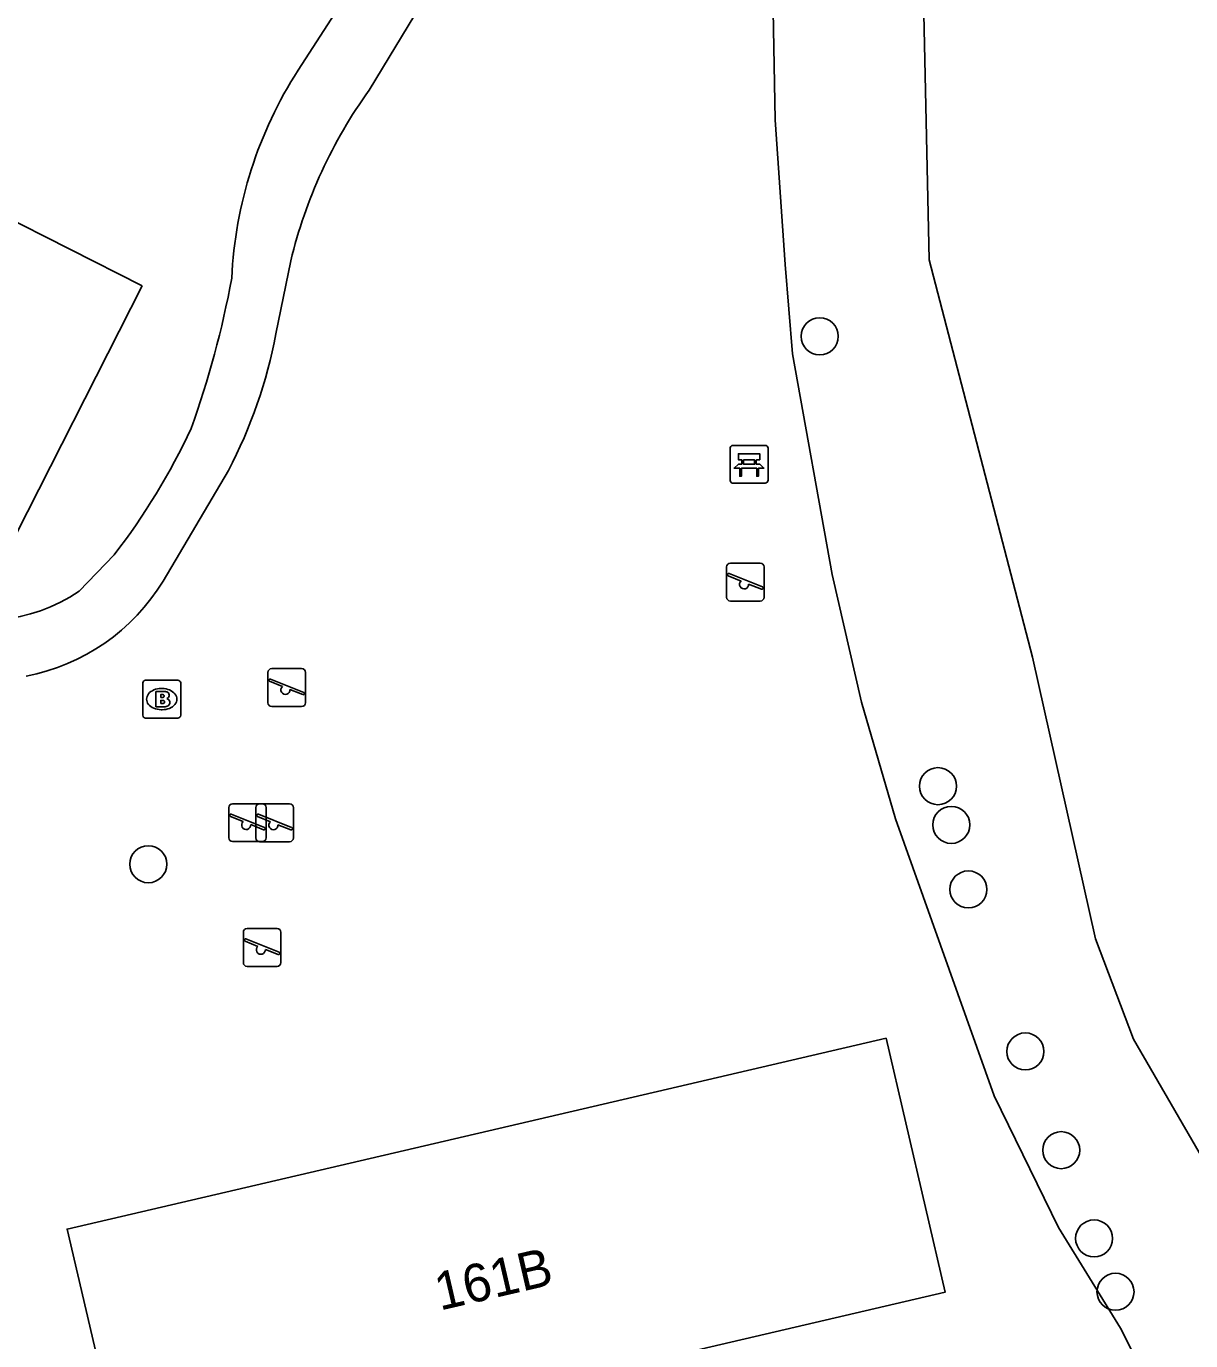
# Model space of a CAD drawing. Extents: x 160203 to 161526, y 379529 to 381797.
# Drawn here: x 161221.44 to 161252.18, y 381451.92 to 381486.62 of the extents above; entities that cross this region are included whole.
import ezdxf

# ---------------------------------------------------------------- set-up
doc = ezdxf.new("R2010")
doc.units = 0
for name, color, linetype in [('IMGEO_Bank', 7, 'Continuous'), ('IMGEO_Boom', 7, 'Continuous'), ('IMGEO_Brandkraan', 7, 'Continuous'), ('IMGEO_Groenvoorziening', 7, 'Continuous'), ('IMGEO_Pand', 7, 'Continuous'), ('IMGEO_Pand_nummerreeks', 7, 'Continuous'), ('IMGEO_Speelvoorziening', 7, 'Continuous'), ('IMGEO_Voetpad_halfverhard', 7, 'Continuous'), ('IMGEO_Waterloop', 7, 'Continuous')]:
    doc.layers.add(name, color=color, linetype=linetype)

msp = doc.modelspace()

# ---------------------------------------------------------------- linework, layer by layer
at = {"layer": 'IMGEO_Bank'}
for p, q in [((161240.024, 381474.633), (161240.024, 381475.474)), ((161240.024, 381475.474), (161240.024, 381474.633)), ((161240.099, 381475.558), (161240.94, 381475.558)), ((161240.94, 381475.558), (161240.099, 381475.558)), ((161241.024, 381475.483), (161241.024, 381474.642)), ((161241.024, 381474.642), (161241.024, 381475.483)), ((161240.333, 381475.064), (161240.333, 381475.17)), ((161240.377, 381475.17), (161240.377, 381475.064)), ((161240.665, 381475.176), (161240.383, 381475.176)), ((161240.671, 381475.064), (161240.671, 381475.17)), ((161240.715, 381475.17), (161240.715, 381475.064)), ((161240.721, 381474.956), (161240.328, 381474.956)), ((161240.383, 381475.058), (161240.665, 381475.058)), ((161240.949, 381474.558), (161240.108, 381474.558)), ((161240.108, 381474.558), (161240.949, 381474.558))]:
    msp.add_line(p, q, dxfattribs=at)
for points in [[(161240.327, 381475.176), (161240.241, 381475.176), (161240.241, 381475.337), (161240.804, 381475.337), (161240.804, 381475.176), (161240.721, 381475.176)], [(161240.271, 381474.956), (161240.129, 381474.956), (161240.241, 381475.058), (161240.327, 381475.058)], [(161240.321, 381474.949), (161240.321, 381474.742), (161240.278, 381474.742), (161240.278, 381474.949)], [(161240.721, 381475.058), (161240.804, 381475.058), (161240.916, 381474.956), (161240.777, 381474.956)], [(161240.771, 381474.949), (161240.771, 381474.742), (161240.727, 381474.742), (161240.727, 381474.949)]]:
    msp.add_lwpolyline(points, dxfattribs=at)
for centre, radius, start, end in [((161240.102, 381475.48), 0.0779, 92.4484, 184.2845), ((161240.102, 381475.48), 0.0779, 92.4484, 184.2845), ((161240.946, 381475.48), 0.0779, 2.4484, 94.2845), ((161240.946, 381475.48), 0.0779, 2.4484, 94.2845), ((161240.326, 381475.169), 0.00671, 2.8957, 87.1043), ((161240.383, 381475.169), 0.00671, 92.8957, 177.1043), ((161240.665, 381475.169), 0.00671, 2.8957, 87.1043), ((161240.722, 381475.169), 0.00671, 92.8957, 177.1043), ((161240.271, 381474.949), 0.00671, 2.8957, 87.1043), ((161240.328, 381474.949), 0.00671, 92.8957, 177.1043), ((161240.326, 381475.065), 0.00671, 272.8957, 357.1043), ((161240.383, 381475.065), 0.00671, 182.8957, 267.1043), ((161240.665, 381475.065), 0.00671, 272.8957, 357.1043), ((161240.722, 381475.065), 0.00671, 182.8957, 267.1043), ((161240.72, 381474.949), 0.00671, 2.8957, 87.1043), ((161240.777, 381474.949), 0.00671, 92.8957, 177.1043), ((161240.102, 381474.636), 0.0779, 182.4484, 274.2845), ((161240.102, 381474.636), 0.0779, 182.4484, 274.2845), ((161240.946, 381474.636), 0.0779, 272.4484, 4.2845), ((161240.946, 381474.636), 0.0779, 272.4484, 4.2845)]:
    msp.add_arc(centre, radius, start, end, dxfattribs=at)
at = {"layer": 'IMGEO_Boom'}
for centre in [(161242.389, 381478.437), (161245.511, 381466.559), (161245.862, 381465.537), (161224.663, 381464.498), (161246.314, 381463.832), (161247.818, 381459.553), (161248.765, 381456.947), (161249.632, 381454.617), (161250.198, 381453.207)]:
    msp.add_circle(centre, 0.489, dxfattribs=at)
at = {"layer": 'IMGEO_Brandkraan'}
for p, q in [((161224.517, 381468.431), (161224.517, 381469.283)), ((161224.592, 381469.357), (161225.444, 381469.357)), ((161225.518, 381469.283), (161225.518, 381468.431)), ((161225.005, 381469.137), (161225.03, 381469.137)), ((161225.028, 381468.577), (161225.003, 381468.577)), ((161225.444, 381468.357), (161224.592, 381468.357))]:
    msp.add_line(p, q, dxfattribs=at)
for points in [[(161224.517, 381468.431), (161224.517, 381469.283)], [(161224.592, 381469.357), (161225.444, 381469.357)], [(161225.518, 381469.283), (161225.518, 381468.431)], [(161224.865, 381469.057), (161224.865, 381468.657), (161225.078, 381468.657)], [(161225.096, 381469.057), (161224.865, 381469.057)], [(161225.044, 381468.976), (161224.99, 381468.976), (161224.99, 381468.9)], [(161224.99, 381468.9), (161225.043, 381468.9)], [(161225.052, 381468.824), (161224.99, 381468.824), (161224.99, 381468.743)], [(161224.99, 381468.743), (161225.052, 381468.743)], [(161225.444, 381468.357), (161224.592, 381468.357)]]:
    msp.add_lwpolyline(points, dxfattribs=at)
for centre, radius, start, end in [((161224.594, 381469.281), 0.0765, 91.552, 178.448), ((161224.594, 381469.281), 0.0765, 91.552, 178.448), ((161225.442, 381469.281), 0.0765, 1.552, 88.448), ((161225.442, 381469.281), 0.0765, 1.552, 88.448), ((161225.045, 381468.938), 0.0379, 267.8285, 90.9355), ((161225.1, 381468.912), 0.145, 59.4692, 91.5367), ((161225.125, 381468.959), 0.0922, 285.5137, 58.1501), ((161225.13, 381468.767), 0.105, 301.3115, 78.989), ((161225.053, 381468.783), 0.0404, 269.8759, 90.5077), ((161225.084, 381468.908), 0.251, 268.6676, 293.5347), ((161224.594, 381468.433), 0.0765, 181.552, 268.448), ((161224.594, 381468.433), 0.0765, 181.552, 268.448), ((161225.442, 381468.433), 0.0765, 271.552, 358.448), ((161225.442, 381468.433), 0.0765, 271.552, 358.448)]:
    msp.add_arc(centre, radius, start, end, dxfattribs=at)
for centre, major_axis, ratio, start_param, end_param in [((161225.004, 381468.857), (-0.387, 0.002), 0.722429, 4.712389, 7.853982), ((161225.029, 381468.857), (-0.39, 0.002), 0.717154, 1.570796, 4.712389)]:
    msp.add_ellipse(centre, major_axis=major_axis, ratio=ratio, start_param=start_param, end_param=end_param, dxfattribs=at)
at = {"layer": 'IMGEO_Groenvoorziening'}
msp.add_lwpolyline([(161251.542, 381449.834), (161250.332, 381452.25), (161248.694, 381454.902), (161246.993, 381458.38), (161244.393, 381465.694), (161243.49, 381468.776), (161242.716, 381472.152), (161241.669, 381477.972), (161241.479, 381480.337), (161241.215, 381484.157), (161241.154, 381487.512), (161241.535, 381491.561), (161242.183, 381495.839), (161242.989, 381500), (161246.33, 381520.277), (161246.842, 381523.523), (161247.568, 381527.981)], dxfattribs=at)
at = {"layer": 'IMGEO_Pand'}
for points in [[(161224.501, 381479.774), (161220.87, 381472.604), (161207.498, 381479.375), (161211.129, 381486.545), (161224.501, 381479.774)], [(161244.142, 381459.903), (161245.705, 381453.198), (161224.084, 381448.157), (161222.52, 381454.862), (161244.142, 381459.903)]]:
    msp.add_lwpolyline(points, dxfattribs=at)
at = {"layer": 'IMGEO_Speelvoorziening'}
for p, q in [((161239.93, 381471.548), (161239.93, 381472.348)), ((161239.93, 381472.348), (161239.93, 381471.548)), ((161240.03, 381472.448), (161240.82, 381472.448)), ((161240.82, 381472.448), (161240.03, 381472.448)), ((161240.92, 381472.348), (161240.92, 381471.548)), ((161240.92, 381471.548), (161240.92, 381472.348)), ((161240.313, 381471.976), (161239.974, 381472.113)), ((161239.999, 381472.173), (161240.875, 381471.82)), ((161240.851, 381471.76), (161240.511, 381471.897)), ((161240.82, 381471.448), (161240.03, 381471.448)), ((161240.03, 381471.448), (161240.82, 381471.448)), ((161227.822, 381468.763), (161227.822, 381469.563)), ((161227.822, 381469.563), (161227.822, 381468.763)), ((161227.922, 381469.663), (161228.712, 381469.663)), ((161228.712, 381469.663), (161227.922, 381469.663)), ((161228.812, 381469.563), (161228.812, 381468.763)), ((161228.812, 381468.763), (161228.812, 381469.563)), ((161228.205, 381469.191), (161227.866, 381469.328)), ((161227.891, 381469.388), (161228.767, 381469.035)), ((161228.743, 381468.975), (161228.403, 381469.112)), ((161228.712, 381468.663), (161227.922, 381468.663)), ((161227.922, 381468.663), (161228.712, 381468.663)), ((161226.886, 381466.095), (161227.676, 381466.095)), ((161227.676, 381466.095), (161226.886, 381466.095)), ((161227.603, 381466.091), (161228.393, 381466.091)), ((161228.393, 381466.091), (161227.603, 381466.091)), ((161226.786, 381465.195), (161226.786, 381465.995)), ((161226.786, 381465.995), (161226.786, 381465.195)), ((161227.169, 381465.623), (161226.83, 381465.76)), ((161226.855, 381465.82), (161227.731, 381465.467)), ((161227.503, 381465.191), (161227.503, 381465.991)), ((161227.503, 381465.991), (161227.503, 381465.191)), ((161227.886, 381465.619), (161227.547, 381465.756)), ((161227.572, 381465.816), (161228.448, 381465.463)), ((161227.776, 381465.995), (161227.776, 381465.195)), ((161227.776, 381465.195), (161227.776, 381465.995)), ((161228.493, 381465.991), (161228.493, 381465.191)), ((161228.493, 381465.191), (161228.493, 381465.991)), ((161227.707, 381465.407), (161227.367, 381465.544)), ((161228.424, 381465.403), (161228.084, 381465.54)), ((161227.676, 381465.095), (161226.886, 381465.095)), ((161226.886, 381465.095), (161227.676, 381465.095)), ((161228.393, 381465.091), (161227.603, 381465.091)), ((161227.603, 381465.091), (161228.393, 381465.091)), ((161227.172, 381461.9), (161227.172, 381462.7)), ((161227.172, 381462.7), (161227.172, 381461.9)), ((161227.272, 381462.8), (161228.062, 381462.8)), ((161228.062, 381462.8), (161227.272, 381462.8)), ((161228.162, 381462.7), (161228.162, 381461.9)), ((161228.162, 381461.9), (161228.162, 381462.7)), ((161227.555, 381462.328), (161227.216, 381462.465)), ((161227.241, 381462.525), (161228.117, 381462.172)), ((161228.093, 381462.112), (161227.753, 381462.249)), ((161228.062, 381461.8), (161227.272, 381461.8)), ((161227.272, 381461.8), (161228.062, 381461.8))]:
    msp.add_line(p, q, dxfattribs=at)
for centre, radius, start, end in [((161240.03, 381472.348), 0.1, 90, 180), ((161240.03, 381472.348), 0.1, 90, 180), ((161240.82, 381472.348), 0.1, 0, 90), ((161240.82, 381472.348), 0.1, 360, 90), ((161239.987, 381472.143), 0.0327, 68.078, 248.078), ((161240.392, 381471.886), 0.12, 130.9928, 5.1632), ((161240.863, 381471.79), 0.0327, 248.078, 68.078), ((161240.03, 381471.548), 0.1, 180, 270), ((161240.03, 381471.548), 0.1, 180, 270), ((161240.82, 381471.548), 0.1, 270, 0), ((161240.82, 381471.548), 0.1, 270, 0), ((161227.922, 381469.563), 0.1, 90, 180), ((161227.922, 381469.563), 0.1, 90, 180), ((161228.712, 381469.563), 0.1, 0, 90), ((161228.712, 381469.563), 0.1, 360, 90), ((161227.879, 381469.358), 0.0327, 68.078, 248.078), ((161228.284, 381469.101), 0.12, 130.9928, 5.1632), ((161228.755, 381469.005), 0.0327, 248.078, 68.078), ((161227.922, 381468.763), 0.1, 180, 270), ((161227.922, 381468.763), 0.1, 180, 270), ((161228.712, 381468.763), 0.1, 270, 0), ((161228.712, 381468.763), 0.1, 270, 0), ((161226.886, 381465.995), 0.1, 90, 180), ((161226.886, 381465.995), 0.1, 90, 180), ((161227.603, 381465.991), 0.1, 90, 180), ((161227.603, 381465.991), 0.1, 90, 180), ((161227.676, 381465.995), 0.1, 0, 90), ((161227.676, 381465.995), 0.1, 360, 90), ((161228.393, 381465.991), 0.1, 0, 90), ((161228.393, 381465.991), 0.1, 360, 90), ((161226.843, 381465.79), 0.0327, 68.078, 248.078), ((161227.56, 381465.786), 0.0327, 68.078, 248.078), ((161227.248, 381465.533), 0.12, 130.9928, 5.1632), ((161227.719, 381465.437), 0.0327, 248.078, 68.078), ((161227.965, 381465.529), 0.12, 130.9928, 5.1632), ((161228.436, 381465.433), 0.0327, 248.078, 68.078), ((161226.886, 381465.195), 0.1, 180, 270), ((161226.886, 381465.195), 0.1, 180, 270), ((161227.603, 381465.191), 0.1, 180, 270), ((161227.603, 381465.191), 0.1, 180, 270), ((161227.676, 381465.195), 0.1, 270, 0), ((161227.676, 381465.195), 0.1, 270, 0), ((161228.393, 381465.191), 0.1, 270, 0), ((161228.393, 381465.191), 0.1, 270, 0), ((161227.272, 381462.7), 0.1, 90, 180), ((161227.272, 381462.7), 0.1, 90, 180), ((161228.062, 381462.7), 0.1, 0, 90), ((161228.062, 381462.7), 0.1, 360, 90), ((161227.229, 381462.495), 0.0327, 68.078, 248.078), ((161227.634, 381462.238), 0.12, 130.9928, 5.1632), ((161228.105, 381462.142), 0.0327, 248.078, 68.078), ((161227.272, 381461.9), 0.1, 180, 270), ((161227.272, 381461.9), 0.1, 180, 270), ((161228.062, 381461.9), 0.1, 270, 0), ((161228.062, 381461.9), 0.1, 270, 0)]:
    msp.add_arc(centre, radius, start, end, dxfattribs=at)
at = {"layer": 'IMGEO_Voetpad_halfverhard'}
for points in [[(161237.943, 381498.945), (161236.454, 381495.503), (161234.671, 381492.091), (161233.43, 381489.795), (161230.495, 381484.939)], [(161228.619, 381485.465), (161232.589, 381491.606), (161233.892, 381493.762), (161234.9, 381495.964)], [(161228.426, 381480.434), (161228.034, 381478.501)], [(161226.777, 381474.892), (161225.055, 381471.976)], [(161222.834, 381471.708), (161223.764, 381472.67)]]:
    msp.add_lwpolyline(points, dxfattribs=at)
for centre, radius, start, end in [((161237.943, 381479.463), 11.088, 147.2293, 177.3594), ((161240.932, 381477.418), 12.865, 144.2232, 166.4412), ((161201.399, 381484.709), 25.904, 340.3639, 349.468), ((161215.217, 381480.942), 13.047, 332.3755, 349.2185), ((161209.554, 381483.617), 17.937, 322.3904, 334.8868), ((161220.412, 381474.797), 5.433, 280.9275, 328.7131), ((161220.341, 381475.339), 4.404, 245.5993, 304.4732)]:
    msp.add_arc(centre, radius, start, end, dxfattribs=at)
at = {"layer": 'IMGEO_Waterloop'}
msp.add_lwpolyline([(161252.539, 381530.425), (161252.368, 381529.663), (161250.972, 381521.806), (161250.64, 381519.933), (161247.099, 381500), (161246.333, 381495.686), (161245.704, 381493.213), (161245.597, 381491.231), (161245.711, 381488.819), (161245.14, 381486.953), (161245.28, 381480.454), (161248.009, 381469.969), (161249.672, 381462.531), (161250.675, 381459.878), (161256.133, 381450.459)], dxfattribs=at)

# ---------------------------------------------------------------- texts
at = {"layer": 'IMGEO_Pand_nummerreeks'}
msp.add_text('161B', height=1, rotation=13.0614, dxfattribs=at).set_placement((161232.361, 381452.708))

doc.saveas('drawing.dxf')
